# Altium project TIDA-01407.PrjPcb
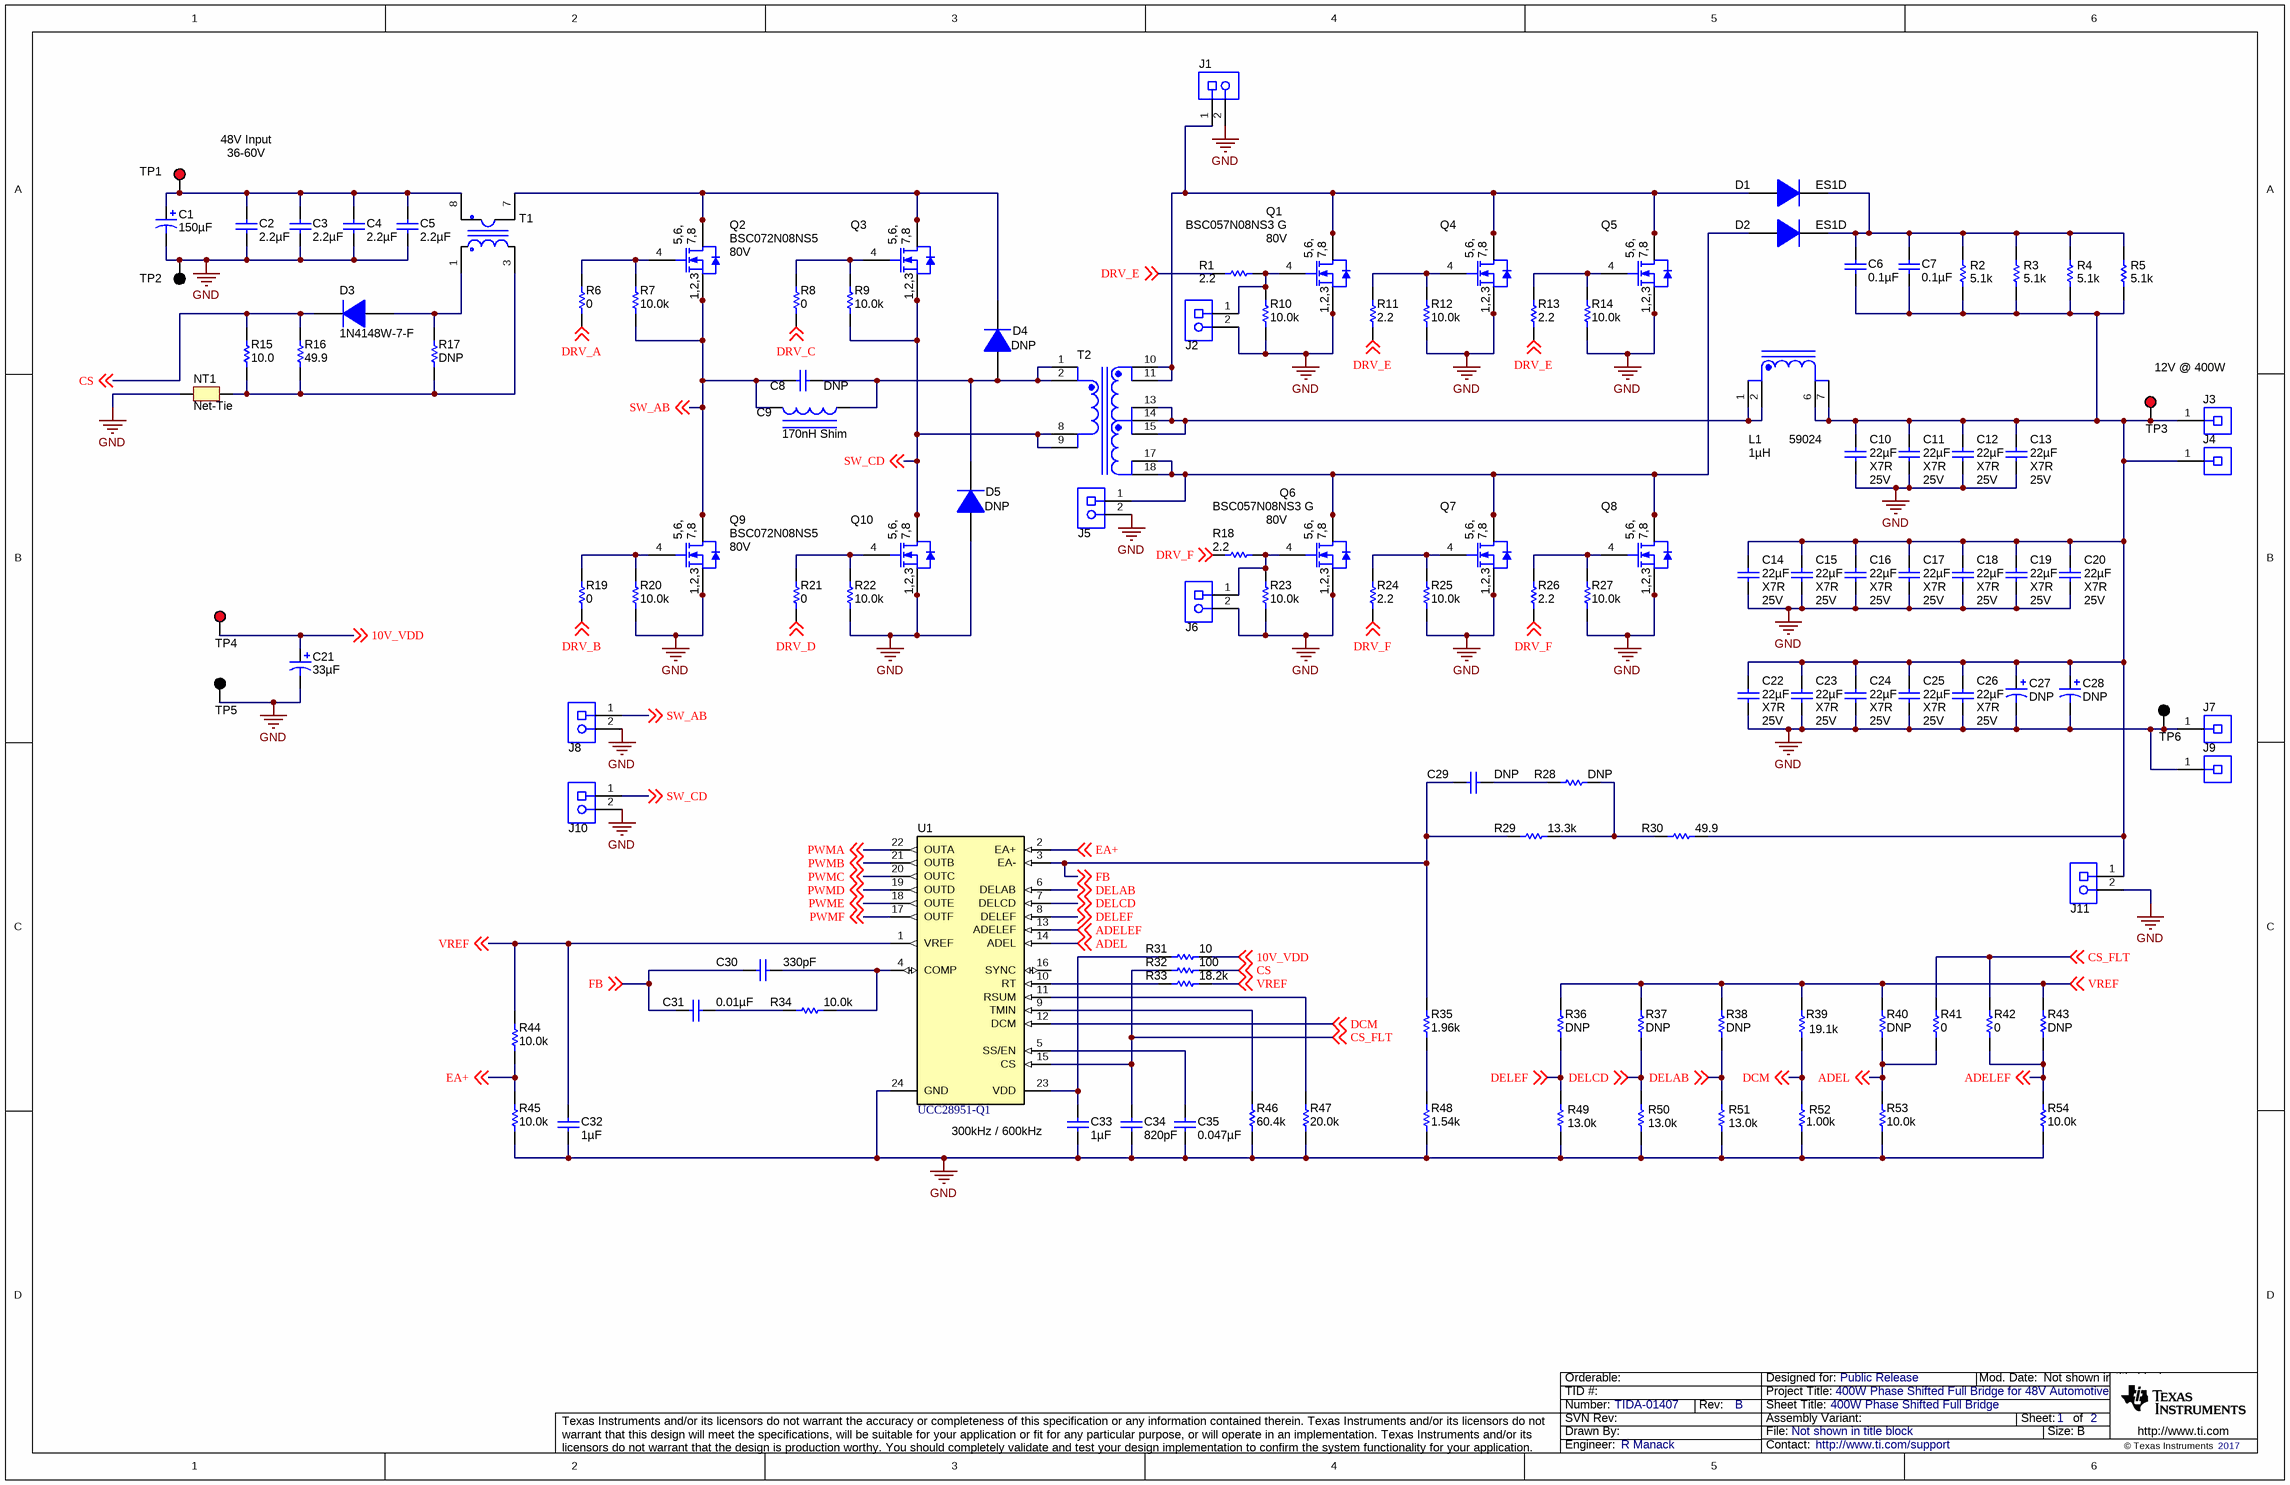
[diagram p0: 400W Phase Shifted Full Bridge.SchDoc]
CopyrightYear: 2017; PCB_Layout: R Manack; PCB_Rev: B; PRJ_Customer: Public Release; PRJ_Engineer: R Manack; PRJ_Number: TIDA-01407; PRJ_Title: 400W Phase Shifted Full Bridge for 48V Automotive; SCH_Rev: B; TechSupport: http://www.ti.com/support
2 sheets, 145 parts. Net scope: global (net labels, ports and power ports of the same name join across sheets).
Board file: TIDA-01407.PcbDoc
Sheets:
  400W Phase Shifted Full Bridge.SchDoc
  Gate Drivers High Side and Low Side.SchDoc

## Sheet 400W Phase Shifted Full Bridge.SchDoc: 400W Phase Shifted Full Bridge
size 431 x 279 mm; Date: Not shown in title block; ApprovedBy: Not shown in title block; CheckedBy: Not shown in title block; Author: Not shown in title block; CompanyName: Not shown in title block; Engineer: Not shown in title block; Organization: Not shown in title block; Address1: Not shown in title block; Address2: Not shown in title block; Address3: Not shown in title block; Address4: Not shown in title block; DocumentNumber: 1; Revision: Use project parameter SCH_Rev; SheetNumber: 1; SheetTotal: 2; PageSetup: Record=PageOptions¦CenterHorizontal=True¦CenterVertical=True¦PrintScale=1.00¦XCorrection=1.00¦YCorrection=1.00¦PrintKind=0¦BorderSize=5000000¦LeftOffset=0¦BottomOffset=0¦Orientation=2¦PaperLength=1000¦PaperWidth=1000¦Scale=100¦PaperSource=15¦PrintQuality=600¦MediaType=1¦DitherType=10¦PaperKind=Letter¦PrintScaleMode=1

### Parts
C1  ValueDisplayed: 150µF  [SM_RADIAL_J16]  (hidden comment: EEV-FK2A151M)
C2  ValueDisplayed: 2.2µF  [1210_270]  (hidden comment: GRM32ER72A225KA35L)
C3  ValueDisplayed: 2.2µF  [1210_270]  (hidden comment: GRM32ER72A225KA35L)
C4  ValueDisplayed: 2.2µF  [1210_270]  (hidden comment: GRM32ER72A225KA35L)
C5  ValueDisplayed: 2.2µF  [1210_270]  (hidden comment: GRM32ER72A225KA35L)
C6  ValueDisplayed: 0.1µF  [1206_180]  (hidden comment: GRM31CR72E104KW03L)
C7  ValueDisplayed: 0.1µF  [1206_180]  (hidden comment: GRM31CR72E104KW03L)
C8  ValueDisplayed: DNP  [1210_270]  (hidden comment: GRM32ER72A225KA35L)
C9  ValueDisplayed: 170nH Shim  [DFE322512C]  (hidden comment: 170nH Custom Shim)
C10  ValueDisplayed: 22µF  Value2: 25V  TempCo: X7R  [1210_270L]  (hidden comment: GRM32ER71E226KE15L)
C11  ValueDisplayed: 22µF  Value2: 25V  TempCo: X7R  [1210_270L]  (hidden comment: GRM32ER71E226KE15L)
C12  ValueDisplayed: 22µF  Value2: 25V  TempCo: X7R  [1210_270L]  (hidden comment: GRM32ER71E226KE15L)
C13  ValueDisplayed: 22µF  Value2: 25V  TempCo: X7R  [1210_270L]  (hidden comment: GRM32ER71E226KE15L)
C14  ValueDisplayed: 22µF  Value2: 25V  TempCo: X7R  [1210_270L]  (hidden comment: GRM32ER71E226KE15L)
C15  ValueDisplayed: 22µF  Value2: 25V  TempCo: X7R  [1210_270L]  (hidden comment: GRM32ER71E226KE15L)
C16  ValueDisplayed: 22µF  Value2: 25V  TempCo: X7R  [1210_270L]  (hidden comment: GRM32ER71E226KE15L)
C17  ValueDisplayed: 22µF  Value2: 25V  TempCo: X7R  [1210_270L]  (hidden comment: GRM32ER71E226KE15L)
C18  ValueDisplayed: 22µF  Value2: 25V  TempCo: X7R  [1210_270L]  (hidden comment: GRM32ER71E226KE15L)
C19  ValueDisplayed: 22µF  Value2: 25V  TempCo: X7R  [1210_270L]  (hidden comment: GRM32ER71E226KE15L)
C20  ValueDisplayed: 22µF  Value2: 25V  TempCo: X7R  [1210_270L]  (hidden comment: GRM32ER71E226KE15L)
C21  ValueDisplayed: 33µF  [Chemi-Con_500x1100]  (hidden comment: EKZE350ELL330ME11D)
C22  ValueDisplayed: 22µF  Value2: 25V  TempCo: X7R  [1210_270L]  (hidden comment: GRM32ER71E226KE15L)
C23  ValueDisplayed: 22µF  Value2: 25V  TempCo: X7R  [1210_270L]  (hidden comment: GRM32ER71E226KE15L)
C24  ValueDisplayed: 22µF  Value2: 25V  TempCo: X7R  [1210_270L]  (hidden comment: GRM32ER71E226KE15L)
C25  ValueDisplayed: 22µF  Value2: 25V  TempCo: X7R  [1210_270L]  (hidden comment: GRM32ER71E226KE15L)
C26  ValueDisplayed: 22µF  Value2: 25V  TempCo: X7R  [1210_270L]  (hidden comment: GRM32ER71E226KE15L)
C27  ValueDisplayed: DNP  [7343-31]  (hidden comment: 16TQC150MYF)
C28  ValueDisplayed: DNP  [7343-31]  (hidden comment: 16TQC150MYF)
C29  ValueDisplayed: DNP  [0603L]  (hidden comment: GRM1885C1H470JA01D)
C30  ValueDisplayed: 330pF  [0603]  (hidden comment: GRM1885C1H331JA01D)
C31  ValueDisplayed: 0.01µF  [0603L]  (hidden comment: GRM188R71H103KA01D)
C32  ValueDisplayed: 1µF  [0603L]  (hidden comment: GRM188R71E105KA12D)
C33  ValueDisplayed: 1µF  [0603L]  (hidden comment: GRM188R71E105KA12D)
C34  ValueDisplayed: 820pF  [0603L]  (hidden comment: GRM1885C1H821JA01D)
C35  ValueDisplayed: 0.047µF  [0603L]  (hidden comment: GRM188R71H473KA61D)
D1  ES1D  [SMA]
D2  ES1D  [SMA]
D3  1N4148W-7-F  [SOD-123]
D4  PartNumber: DNP  [SMA]  (hidden comment: ES1D)
D5  PartNumber: DNP  [SMA]  (hidden comment: ES1D)
J1  PPTC021LFBN-RC  [CONN_PPTC021LFBN-RC]  (value not drawn)
J2  PPTC021LFBN-RC  [CONN_PPTC021LFBN-RC]  (value not drawn)
J3  L35  [TB_L35]  (value not drawn)
J4  L35  [TB_L35]  (value not drawn)
J5  PPTC021LFBN-RC  [CONN_PPTC021LFBN-RC]  (value not drawn)
J6  PPTC021LFBN-RC  [CONN_PPTC021LFBN-RC]  (value not drawn)
J7  L35  [TB_L35]  (value not drawn)
J8  PPTC021LFBN-RC  [CONN_PPTC021LFBN-RC]  (value not drawn)
J9  L35  [TB_L35]  (value not drawn)
J10  PPTC021LFBN-RC  [CONN_PPTC021LFBN-RC]  (value not drawn)
J11  PPTC021LFBN-RC  [CONN_PPTC021LFBN-RC]  (value not drawn)
L1  59024  ValueDisplayed: 1µH  [59024]
NT1  Net-Tie  [Net-Tie_50milWide_30milLong]  (net tie, no BOM)
Q1  BSC057N08NS3 G  value 80V  [PG-TDSON-8]
Q2  BSC072N08NS5  value 80V  [PG-TDSON-8]
Q3  BSC072N08NS5  [PG-TDSON-8]  (value not drawn)
Q4  BSC057N08NS3 G  [PG-TDSON-8]  (value not drawn)
Q5  BSC057N08NS3 G  [PG-TDSON-8]  (value not drawn)
Q6  BSC057N08NS3 G  value 80V  [PG-TDSON-8]
Q7  BSC057N08NS3 G  [PG-TDSON-8]  (value not drawn)
Q8  BSC057N08NS3 G  [PG-TDSON-8]  (value not drawn)
Q9  BSC072N08NS5  value 80V  [PG-TDSON-8]
Q10  BSC072N08NS5  [PG-TDSON-8]  (value not drawn)
R1  ValueDisplayed: 2.2  [0603L]  (hidden comment: CRCW06032R20JNEA)
R2  ValueDisplayed: 5.1k  [2512]  (hidden comment: CRCW25125K10JNEH)
R3  ValueDisplayed: 5.1k  [2512]  (hidden comment: CRCW25125K10JNEH)
R4  ValueDisplayed: 5.1k  [2512]  (hidden comment: CRCW25125K10JNEH)
R5  ValueDisplayed: 5.1k  [2512]  (hidden comment: CRCW25125K10JNEH)
R6  ValueDisplayed: 0  [0603L]  (hidden comment: CRCW06030000Z0EA)
R7  ValueDisplayed: 10.0k  [0603L]  (hidden comment: CRCW060310K0FKEA)
R8  ValueDisplayed: 0  [0603L]  (hidden comment: CRCW06030000Z0EA)
R9  ValueDisplayed: 10.0k  [0603L]  (hidden comment: CRCW060310K0FKEA)
R10  ValueDisplayed: 10.0k  [0603L]  (hidden comment: CRCW060310K0FKEA)
R11  ValueDisplayed: 2.2  [0603L]  (hidden comment: CRCW06032R20JNEA)
R12  ValueDisplayed: 10.0k  [0603L]  (hidden comment: CRCW060310K0FKEA)
R13  ValueDisplayed: 2.2  [0603L]  (hidden comment: CRCW06032R20JNEA)
R14  ValueDisplayed: 10.0k  [0603L]  (hidden comment: CRCW060310K0FKEA)
R15  ValueDisplayed: 10.0  [1206]  (hidden comment: CRCW120610R0FKEA)
R16  ValueDisplayed: 49.9  [1206]  (hidden comment: CRCW120649R9FKEA)
R17  ValueDisplayed: DNP  [0603L]  (hidden comment: CRCW060310K0FKEA)
R18  ValueDisplayed: 2.2  [0603L]  (hidden comment: CRCW06032R20JNEA)
R19  ValueDisplayed: 0  [0603L]  (hidden comment: CRCW06030000Z0EA)
R20  ValueDisplayed: 10.0k  [0603L]  (hidden comment: CRCW060310K0FKEA)
R21  ValueDisplayed: 0  [0603L]  (hidden comment: CRCW06030000Z0EA)
R22  ValueDisplayed: 10.0k  [0603L]  (hidden comment: CRCW060310K0FKEA)
R23  ValueDisplayed: 10.0k  [0603L]  (hidden comment: CRCW060310K0FKEA)
R24  ValueDisplayed: 2.2  [0603L]  (hidden comment: CRCW06032R20JNEA)
R25  ValueDisplayed: 10.0k  [0603L]  (hidden comment: CRCW060310K0FKEA)
R26  ValueDisplayed: 2.2  [0603L]  (hidden comment: CRCW06032R20JNEA)
R27  ValueDisplayed: 10.0k  [0603L]  (hidden comment: CRCW060310K0FKEA)
R28  ValueDisplayed: DNP  [0603L]  (hidden comment: CRCW06030000Z0EA)
R29  ValueDisplayed: 13.3k  [0603L]  (hidden comment: CRCW060313K3FKEA)
R30  ValueDisplayed: 49.9  [0603L]  (hidden comment: CRCW060349R9FKEA)
R31  ValueDisplayed: 10  [0603L]  (hidden comment: CRCW060310R0JNEA)
R32  ValueDisplayed: 100  [0603L]  (hidden comment: CRCW0603100RFKEA)
R33  ValueDisplayed: 18.2k  [0603L]  (hidden comment: CRCW060318K2FKEA)
R34  ValueDisplayed: 10.0k  [0603L]  (hidden comment: CRCW060310K0FKEA)
R35  ValueDisplayed: 1.96k  [0603L]  (hidden comment: CRCW06031K96FKEA)
R36  ValueDisplayed: DNP  [0603L]  (hidden comment: CRCW060310K0FKEA)
R37  ValueDisplayed: DNP  [0603L]  (hidden comment: CRCW060310K0FKEA)
R38  ValueDisplayed: DNP  [0603L]  (hidden comment: CRCW060310K0FKEA)
R39  ValueDisplayed: 19.1k  [0603L]  (hidden comment: CRCW060319K1FKEA)
R40  ValueDisplayed: DNP  [0603L]  (hidden comment: CRCW060310K0FKEA)
R41  ValueDisplayed: 0  [0603L]  (hidden comment: CRCW06030000Z0EA)
R42  ValueDisplayed: 0  [0603L]  (hidden comment: CRCW06030000Z0EA)
R43  ValueDisplayed: DNP  [0603L]  (hidden comment: CRCW060310K0FKEA)
R44  ValueDisplayed: 10.0k  [0603L]  (hidden comment: CRCW060310K0FKEA)
R45  ValueDisplayed: 10.0k  [0603L]  (hidden comment: CRCW060310K0FKEA)
R46  ValueDisplayed: 60.4k  [0603L]  (hidden comment: CRCW060360K4FKEA)
R47  ValueDisplayed: 20.0k  [0603L]  (hidden comment: CRCW060320K0FKEA)
R48  ValueDisplayed: 1.54k  [0603L]  (hidden comment: CRCW06031K54FKEA)
R49  ValueDisplayed: 13.0k  [0603L]  (hidden comment: RC0603FR-0713KL)
R50  ValueDisplayed: 13.0k  [0603L]  (hidden comment: RC0603FR-0713KL)
R51  ValueDisplayed: 13.0k  [0603L]  (hidden comment: RC0603FR-0713KL)
R52  ValueDisplayed: 1.00k  [0603L]  (hidden comment: CRCW06031K00FKEA)
R53  ValueDisplayed: 10.0k  [0603L]  (hidden comment: CRCW060310K0FKEA)
R54  ValueDisplayed: 10.0k  [0603L]  (hidden comment: CRCW060310K0FKEA)
T1  PA1005.100NL  [P82xx]  (value not drawn)
T2  59023  [Payton_59023]  (value not drawn)
TP1  5000  [Keystone5000]  (value not drawn)
TP2  5001  [Keystone5001]  (value not drawn)
TP3  5000  [Keystone5000]  (value not drawn)
TP4  5000  [Keystone5000]  (value not drawn)
TP5  5001  [Keystone5001]  (value not drawn)
TP6  5001  [Keystone5001]  (value not drawn)
U1  UCC28951-Q1  [PW0024A_N]

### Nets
GND: C1.2(-) C2.2 C3.2 C4.2 C5.2 C10.2 C11.2 C12.2 C13.2 C14.2 C15.2 C16.2 C17.2 C18.2 C19.2 C20.2 C21.2(-) C22.2 C23.2 C24.2 C25.2 C26.2 C27.2(-) C28.2(-) C32.2 C33.2 C34.2 C35.2 D5.2(A) J1.2 J2.2 J5.2 J6.2 J7.1 J8.2 J9.1 J10.2 J11.2 NT1.1 Q1.1(S) Q1.2(S) Q1.3(S) Q4.1(S) Q4.2(S) Q4.3(S) Q5.1(S) Q5.2(S) Q5.3(S) Q6.1(S) Q6.2(S) Q6.3(S) Q7.1(S) Q7.2(S) Q7.3(S) Q8.1(S) Q8.2(S) Q8.3(S) Q9.1(S) Q9.2(S) Q9.3(S) Q10.1(S) Q10.2(S) Q10.3(S) R10.1 R12.1 R14.1 R20.1 R22.1 R23.1 R25.1 R27.1 R45.1 R46.1 R47.1 R48.1 R49.1 R50.1 R51.1 R52.1 R53.1 R54.1 TP2.1 TP5.1 TP6.1 U1.24(GND)
10V_VDD: C21.1(+) R31.2 TP4.1 ; off-sheet 10V_VDD
ADEL: R40.1 R41.1 R53.2 U1.14(ADEL) ; off-sheet ADEL
ADELEF: R42.1 R43.1 R54.2 U1.13(ADELEF) ; off-sheet ADELEF
CS: D3.1(K) R15.2 R16.2 R32.2 ; off-sheet CS
CS_FLT: C34.1 R32.1 R41.2 R42.2 U1.15(CS) ; off-sheet CS_FLT
DCM: R39.1 R52.2 U1.12(DCM) ; off-sheet DCM
DELAB: R38.1 R51.2 U1.6(DELAB) ; off-sheet DELAB
DELCD: R37.1 R50.2 U1.7(DELCD) ; off-sheet DELCD
DELEF: R36.1 R49.2 U1.8(DELEF) ; off-sheet DELEF
DRV_A: R6.1 ; off-sheet DRV_A
DRV_B: R19.1 ; off-sheet DRV_B
DRV_C: R8.1 ; off-sheet DRV_C
DRV_D: R21.1 ; off-sheet DRV_D
DRV_E: R1.2 R11.1 R13.1 ; off-sheet DRV_E
DRV_F: R18.2 R24.1 R26.1 ; off-sheet DRV_F
EA+: R44.1 R45.2 U1.2(EA+) ; off-sheet EA+
FB: C29.1 C30.2 C31.2 R29.1 R35.2 U1.3(EA-) ; off-sheet FB
PWMA: U1.22(OUTA) ; off-sheet PWMA
PWMB: U1.21(OUTB) ; off-sheet PWMB
PWMC: U1.20(OUTC) ; off-sheet PWMC
PWMD: U1.19(OUTD) ; off-sheet PWMD
PWME: U1.18(OUTE) ; off-sheet PWME
PWMF: U1.17(OUTF) ; off-sheet PWMF
SW_AB: C8.1 C9.2 J8.1 Q2.1(S) Q2.2(S) Q2.3(S) Q9.5(D) Q9.6(D) Q9.7(D) Q9.8(D) Q9.9(D) R7.1 ; off-sheet SW_AB
SW_CD: J10.1 Q3.1(S) Q3.2(S) Q3.3(S) Q10.5(D) Q10.6(D) Q10.7(D) Q10.8(D) Q10.9(D) R9.1 T2.8 T2.9 ; off-sheet SW_CD
VREF: C32.1 R33.2 R36.2 R37.2 R38.2 R39.2 R40.2 R43.2 R44.2 U1.1(VREF) ; off-sheet VREF
NetC1_1: C1.1(+) C2.1 C3.1 C4.1 C5.1 T1.8 TP1.1
NetC6_1: C6.1 C7.1 D1.1(K) D2.1(K) R2.2 R3.2 R4.2 R5.2
NetC6_2: C6.2 C7.2 C10.1 C11.1 C12.1 C13.1 C14.1 C15.1 C16.1 C17.1 C18.1 C19.1 C20.1 C22.1 C23.1 C24.1 C25.1 C26.1 C27.1(+) C28.1(+) J3.1 J4.1 J11.1 L1.6 L1.7 R2.1 R3.1 R4.1 R5.1 R30.2 TP3.1
NetC8_2: C8.2 C9.1 D4.2(A) D5.1(K) T2.1 T2.2
NetC29_2: C29.2 R28.2
NetC30_1: C30.1 R34.2 U1.4(COMP)
NetC31_1: C31.1 R34.1
NetC33_1: C33.1 R31.1 U1.23(VDD)
NetC35_1: C35.1 U1.5(SS/EN)
NetD1_2: D1.2(A) J1.1 Q1.5(D) Q1.6(D) Q1.7(D) Q1.8(D) Q1.9(D) Q4.5(D) Q4.6(D) Q4.7(D) Q4.8(D) Q4.9(D) Q5.5(D) Q5.6(D) Q5.7(D) Q5.8(D) Q5.9(D) T2.10 T2.11
NetD2_2: D2.2(A) J5.1 Q6.5(D) Q6.6(D) Q6.7(D) Q6.8(D) Q6.9(D) Q7.5(D) Q7.6(D) Q7.7(D) Q7.8(D) Q7.9(D) Q8.5(D) Q8.6(D) Q8.7(D) Q8.8(D) Q8.9(D) T2.17 T2.18
NetD3_2: D3.2(A) R17.2 T1.1
NetD4_1: D4.1(K) Q2.5(D) Q2.6(D) Q2.7(D) Q2.8(D) Q2.9(D) Q3.5(D) Q3.6(D) Q3.7(D) Q3.8(D) Q3.9(D) T1.7
NetJ2_1: J2.1 Q1.4(G) R1.1 R10.2
NetJ6_1: J6.1 Q6.4(G) R18.1 R23.2
NetL1_1: L1.1 L1.2 T2.13 T2.14 T2.15
NetNT1_2: NT1.2 R15.1 R16.1 R17.1 T1.3
NetQ2_4: Q2.4(G) R6.2 R7.2
NetQ3_4: Q3.4(G) R8.2 R9.2
NetQ4_4: Q4.4(G) R11.2 R12.2
NetQ5_4: Q5.4(G) R13.2 R14.2
NetQ7_4: Q7.4(G) R24.2 R25.2
NetQ8_4: Q8.4(G) R26.2 R27.2
NetQ9_4: Q9.4(G) R19.2 R20.2
NetQ10_4: Q10.4(G) R21.2 R22.2
NetR28_1: R28.1 R29.2 R30.1
NetR33_1: R33.1 U1.10(RT)
NetR35_1: R35.1 R48.2
NetR46_2: R46.2 U1.9(TMIN)
NetR47_2: R47.2 U1.11(RSUM)

Not connected (* = marked no-connect by the designer): U1 16(SYNC)

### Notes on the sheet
- 48V Input
- 36-60V
- 12V @ 400W
- 300kHz / 600kHz

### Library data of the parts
C1 = EEV-FK2A151M: CAP, AL, 150 µF, 100 V, +/- 20%, 0.17 ohm, AEC-Q200 Grade 2, SMD; Manufacturer: Panasonic; Polarized: Y; CompType: Capacitor; Value: 150uF; U/M: EA; Cap_F: 0.00015; Tolerance_%: 20; VDC_V: 100; Value2: 100V; ESR_ohm: 0.17; IRMS_A: 0.793; TaMin_C: -55; TaMax_C: 105; Cap_Case: J16; SizeAreaWB_mm2: 399; SizeArea_mm2: 323; SizeX_mm: 19; SizeY_mm: 17; SizeZ_mm: 16.5; AEC Category: Q200; AEC Grade: 2
C2-C5 = GRM32ER72A225KA35L: CAP, CERM, 2.2 µF, 100 V, +/- 10%, X7R, 1210; Manufacturer: MuRata; Polarized: N; CompType: Capacitor; Value: 2.2uF; U/M: EA; Cap_F: 0.0000022; Tolerance_%: 10; ESR_ohm: 0.007; Value1: 0.007 ohm; VDC_V: 100; Value2: 100V; IRMS_A: 4.4; TaMin_C: -55; TaMax_C: 125; Cap_Case: 1210; SizeArea_mm2: 8; SizeAreaWB_mm2: 14.7; SizeX_mm: 3.2; SizeY_mm: 2.5; SizeZ_mm: 2.7; AEC Category: Q200
C6 C7 = GRM31CR72E104KW03L: CAP, CERM, 0.1 µF, 250 V, +/- 10%, X7R, 1206; Manufacturer: MuRata; Polarized: N; CompType: Capacitor; Value: 0.1uF; U/M: EA; Cap_F: 0.0000001; Tolerance_%: 10; Value1: Unknown; VDC_V: 250; Value2: 250V; TaMin_C: -55; TaMax_C: 125; Cap_Case: 1206; SizeArea_mm2: 5.12; SizeAreaWB_mm2: 10.92; SizeX_mm: 3.2; SizeY_mm: 1.6; SizeZ_mm: 1.8; AEC Category: Q200
C8 = GRM32ER72A225KA35L: CAP, CERM, 2.2 µF, 100 V, +/- 10%, X7R, 1210; Manufacturer: MuRata; Polarized: N; CompType: Capacitor; Value: DNP; U/M: EA; Cap_F: 0.0000022; Tolerance_%: 10; ESR_ohm: 0.007; Value1: 0.007 ohm; VDC_V: 100; Value2: 100V; IRMS_A: 4.4; TaMin_C: -55; TaMax_C: 125; Cap_Case: 1210; SizeArea_mm2: 8; SizeAreaWB_mm2: 14.7; SizeX_mm: 3.2; SizeY_mm: 2.5; SizeZ_mm: 2.7; AEC Category: Q200
C9 = 1277AS-H-R68M=P2: Inductor, Flat Wire, 680 nH, 3.5 A, 0.035 ohm, SMD; Value2: 3.5A; SizeArea_mm2: 9.18; SizeAreaWB_mm2: 16.28; SizeX_mm: 3.4; SizeY_mm: 2.7; SizeZ_mm: 1.2; AEC Category: Q200; AEC Qualified: N; Ind_H: 680.0E-9; Imax_A: 3.5; Irms: 3.5A @ 40C rise; Isat: 4.2A @ 30% inductance drop; DCR_ohm: 0.035
C10-C20 C22-C26 = GRM32ER71E226KE15L: CAP, CERM, 22 µF, 25 V, +/- 10%, X7R, 1210; Manufacturer: MuRata; Polarized: N; CompType: Capacitor; Value: 22uF; U/M: EA; Cap_F: 0.000022; Tolerance_%: 10; Value1: Unknown; VDC_V: 25; TaMin_C: -55; TaMax_C: 125; Cap_Case: 1210; SizeArea_mm2: 8; SizeAreaWB_mm2: 14.7; SizeX_mm: 3.2; SizeY_mm: 2.5; SizeZ_mm: 2.7; AEC Category: Q200
C21 = EKZE350ELL330ME11D: CAP, AL, 33 µF, 35 V, +/- 20%, TH; Manufacturer: Chemi-Con; Polarized: Y; CompType: Capacitor; Value: 33uF; U/M: EA; Cap_F: 0.000033; Tolerance_%: 20; Value1: Unknown; VDC_V: 35; Value2: 35V; IRMS_A: 0.25; TaMin_C: -40; TaMax_C: 105; Cap_Case: 5x11; SizeAreaWB_mm2: 49; SizeArea_mm2: 25; SizeX_mm: 5; SizeZ_mm: 12.5; AEC Category: Q200; AEC Qualified: N
C27 C28 = 16TQC150MYF: CAP, Tantalum Polymer, 150 µF, 16 V, +/- 20%, 0.05 ohm, 7343-31 SMD; Manufacturer: Panasonic; Polarized: Y; CompType: Capacitor; Value: DNP; U/M: EA; Cap_F: 0.00015; Tolerance_%: 20; VDC_V: 16; Value2: 16V; ESR_ohm: 0.05; IRMS_A: 1.8; TaMin_C: -55; TaMax_C: 105; Cap_Case: 7.3x2.8x4.3; SizeAreaWB_mm2: 58.59; SizeArea_mm2: 31.39; SizeX_mm: 7.3; SizeY_mm: 4.3; SizeZ_mm: 3.1; AEC Category: Q200; AEC Qualified: N
C29 = GRM1885C1H470JA01D: CAP, CERM, 47 pF, 50 V, +/- 5%, C0G/NP0, 0603; Manufacturer: MuRata; Polarized: N; CompType: Capacitor; Value: DNP; U/M: EA; Cap_F: 0.000000000047; Tolerance_%: 5; Value1: Unknown; VDC_V: 50; Value2: 50V; TaMin_C: -55; TaMax_C: 125; Cap_Case: 0603; SizeArea_mm2: 1.28; SizeAreaWB_mm2: 4.68; SizeX_mm: 1.6; SizeY_mm: 0.8; SizeZ_mm: 1; AEC Category: Q200
C30 = GRM1885C1H331JA01D: CAP, CERM, 330 pF, 50 V, +/- 5%, C0G/NP0, 0603; Manufacturer: MuRata; Polarized: N; CompType: Capacitor; Value: 330pF; U/M: EA; Cap_F: 0.00000000033; Tolerance_%: 5; Value1: Unknown; VDC_V: 50; Value2: 50V; TaMin_C: -55; TaMax_C: 125; SizeArea_mm2: 1.28; SizeAreaWB_mm2: 4.68; SizeX_mm: 1.6; SizeY_mm: 0.8; SizeZ_mm: 1; AEC Category: Q200
C31 = GRM188R71H103KA01D: CAP, CERM, 0.01 µF, 50 V, +/- 10%, X7R, 0603; Manufacturer: MuRata; Polarized: N; CompType: Capacitor; Value: 0.01uF; U/M: EA; Cap_F: 0.00000001; Tolerance_%: 10; Value1: Unknown; VDC_V: 50; Value2: 50V; TaMin_C: -55; TaMax_C: 125; Cap_Case: 0603; SizeArea_mm2: 1.28; SizeAreaWB_mm2: 4.68; SizeX_mm: 1.6; SizeY_mm: 0.8; SizeZ_mm: 1; AEC Category: Q200
C32 C33 = GRM188R71E105KA12D: CAP, CERM, 1 µF, 25 V, +/- 10%, X7R, 0603; Manufacturer: MuRata; Polarized: N; CompType: Capacitor; Value: 1uF; U/M: EA; Cap_F: 0.000001; Tolerance_%: 10; Value1: Unknown; VDC_V: 25; Value2: 25V; TaMin_C: -55; TaMax_C: 125; Cap_Case: 0603; SizeArea_mm2: 1.28; SizeAreaWB_mm2: 4.68; SizeX_mm: 1.6; SizeY_mm: 0.8; SizeZ_mm: 1; AEC Category: Q200
C34 = GRM1885C1H821JA01D: CAP, CERM, 820 pF, 50 V, +/- 5%, C0G/NP0, 0603; Manufacturer: MuRata; Polarized: N; CompType: Capacitor; Value: 820pF; U/M: EA; Cap_F: 0.00000000082; Tolerance_%: 5; Value1: Unknown; VDC_V: 50; Value2: 50V; TaMin_C: -55; TaMax_C: 125; Cap_Case: 0603; SizeArea_mm2: 1.28; SizeAreaWB_mm2: 4.68; SizeX_mm: 1.6; SizeY_mm: 0.8; SizeZ_mm: 1; AEC Category: Q200
C35 = GRM188R71H473KA61D: CAP, CERM, 0.047 µF, 50 V, +/- 10%, X7R, 0603; Manufacturer: MuRata; Polarized: N; CompType: Capacitor; Value: 0.047uF; U/M: EA; Cap_F: 0.000000047; Tolerance_%: 10; Value1: Unknown; VDC_V: 50; Value2: 50V; TaMin_C: -55; TaMax_C: 125; Cap_Case: 0603; SizeArea_mm2: 1.28; SizeAreaWB_mm2: 4.68; SizeX_mm: 1.6; SizeY_mm: 0.8; SizeZ_mm: 1; AEC Category: Q200
D1 D2 D4 D5 = ES1D-13-F: Diode, Ultrafast, 200 V, 1 A, SMA; Manufacturer: Diodes Inc.; U/M: EA; Vf_V: 0.92; Value: 200V; Value1: 1A; Value2: 0.92V; Io_A: 1; Vr_V: 200; TJmax_C: 150; RJC_CperW: 25; SizeAreaWB_mm2: 37.3428; SizeArea_mm2: 16.3228; SizeX_mm: 5.59; SizeY_mm: 2.92; SizeZ_mm: 2.87; AEC Category: Q101
D3 = 1N4148W-7-F: Diode, Ultrafast, 100 V, 0.15 A, SOD-123; Manufacturer: Diodes Inc.; U/M: EA; Vf_V: 1.25; Value: 100V; Value1: 0.15A; Value2: 1.25V; Io_A: 0.15; Vr_V: 100; TJmax_C: 150; SizeAreaWB_mm2: 13.095; SizeArea_mm2: 6.545; SizeX_mm: 3.85; SizeY_mm: 1.7; SizeZ_mm: 1.35; AEC Category: Q101
J1 J2 J5 J6 J8 J10 J11 = PPTC021LFBN-RC: Receptacle, 100mil, 2x1, Tin, TH; Manufacturer: Sullins Connector Solutions; SymbolCreator: a0412235
J3 J4 J7 J9 = L35: Connector, L Type Copper Single Conductor, TH; Manufacturer: Thomas & Betts; SymbolCreator: a0799628; Gender: Female; Row_Count: 1
L1 = 59024: Inductor, 1 µH, 47 A, TH; Manufacturer: Payton; SymbolCreator: Altium; Ind_H: 1.0E-6; Value: 1uH; Imax_A: 47; Irms: 47A @ C rise; Value2: 47A; AEC Category: Q200; AEC Qualified: N
NT1 = Net-Tie: Single point connection between nets.; SymbolCreator: codlsc
Q1 Q6 = BSC057N08NS3 G: MOSFET, N-CH, 80 V, 100 A, PG-TDSON-8; Manufacturer: Infineon Technologies; Alternate Manufacturer: None; U/M: EA; ChType: N; VdsMax_V: 80; Value1: ? ohm; Value2: 42 nC; QgTyp_nC: 42; Vgs_V: 20; IdsMax_A: 100; SizeAreaWB_mm2: 55.131; SizeArea_mm2: 29.351; SizeX_mm: 5.99; SizeY_mm: 4.9; SizeZ_mm: 1.12; AEC Category: Q101
Q2 Q9 = BSC072N08NS5ATMA1: MOSFET, N-CH, 80 V, 74 A, PG-TDSON-8; Manufacturer: Infineon Technologies; Alternate Manufacturer: None; U/M: EA; ChType: N; VdsMax_V: 80; Value1: ? ohm; Value2: 24 nC; QgTyp_nC: 24; Vgs_V: 20; IdsMax_A: 74; SizeAreaWB_mm2: 55.131; SizeArea_mm2: 29.351; SizeX_mm: 5.99; SizeY_mm: 4.9; SizeZ_mm: 1.12; AEC Category: Q101
Q3 Q10 = BSC072N08NS5ATMA1: MOSFET, N-CH, 80 V, 74 A, PG-TDSON-8; Manufacturer: Infineon Technologies; Alternate Manufacturer: None; U/M: EA; ChType: N; Value: 80V; VdsMax_V: 80; Value1: ? ohm; Value2: 24 nC; QgTyp_nC: 24; Vgs_V: 20; IdsMax_A: 74; SizeAreaWB_mm2: 55.131; SizeArea_mm2: 29.351; SizeX_mm: 5.99; SizeY_mm: 4.9; SizeZ_mm: 1.12; AEC Category: Q101
Q4 Q5 Q7 Q8 = BSC057N08NS3 G: MOSFET, N-CH, 80 V, 100 A, PG-TDSON-8; Manufacturer: Infineon Technologies; Alternate Manufacturer: None; U/M: EA; ChType: N; Value: 80V; VdsMax_V: 80; Value1: ? ohm; Value2: 42 nC; QgTyp_nC: 42; Vgs_V: 20; IdsMax_A: 100; SizeAreaWB_mm2: 55.131; SizeArea_mm2: 29.351; SizeX_mm: 5.99; SizeY_mm: 4.9; SizeZ_mm: 1.12; AEC Category: Q101
R1 R11 R13 R18 R24 R26 = CRCW06032R20JNEA: RES, 2.2, 5%, 0.1 W, 0603; Manufacturer: Vishay-Dale; CompType: Resistor; Value: 2.2; Value_Code: 2R20; Tolerance_%: 5; Power_W: 0.1; Value2: 0.1W; VDC_V: 75; TempCo: 200 ppm/C; SizeArea_mm2: 1.28; SizeX_mm: 1.6; SizeY_mm: 0.8; SizeZ_mm: 1; EIA_Code: E24; U/M: EA; AEC Category: Q200
R2-R5 = CRCW25125K10JNEH: RES, 5.1 k, 5%, 1 W, AEC-Q200 Grade 0, 2512; Manufacturer: Vishay-Dale; CompType: Resistor; Value: 5.1k; Res_ohm: 5100; Value_Code: 5k10; Tolerance_%: 5; Power_W: 1; Value2: 1W; VDC_V: 500; TempCo: 200 ppm/C; SizeArea_mm2: 20.16; SizeX_mm: 6.3; SizeY_mm: 3.2; SizeZ_mm: 0.71; EIA_Code: E24; U/M: EA; AEC Category: Q200; AEC Qualified: Y; AEC Grade: 0
R6 R8 R19 R21 R41 R42 = CRCW06030000Z0EA: RES, 0, 5%, 0.1 W, 0603; Manufacturer: Vishay-Dale; CompType: Resistor; Value: 0; Value_Code: 0000; Tolerance_%: 5; Power_W: 0.1; Value2: 0.1W; VDC_V: 75; TempCo: 200 ppm/C; SizeArea_mm2: 1.28; SizeX_mm: 1.6; SizeY_mm: 0.8; SizeZ_mm: 1; EIA_Code: E24; U/M: EA; AEC Category: Q200
R7 R9 R10 R12 R14 R20 R22 R23 R25 R27 R34 R44 R45 R53 R54 = CRCW060310K0FKEA: RES, 10.0 k, 1%, 0.1 W, 0603; Manufacturer: Vishay-Dale; CompType: Resistor; Value: 10.0k; Res_ohm: 10000; Value_Code: 10k0; Tolerance_%: 1; Power_W: 0.1; Value2: 0.1W; VDC_V: 75; TempCo: 100 ppm/C; SizeArea_mm2: 1.28; SizeX_mm: 1.6; SizeY_mm: 0.8; EIA_Code: E96; U/M: EA; AEC Category: Q200
R15 = CRCW120610R0FKEA: RES, 10.0, 1%, 0.25 W, 1206; Manufacturer: Vishay-Dale; CompType: Resistor; Value: 10.0; Res_ohm: 10; Value_Code: 10R0; Tolerance_%: 1; Power_W: 0.25; Value2: 0.25W; VDC_V: 200; TempCo: 100 ppm/C; SizeArea_mm2: 5.12; SizeX_mm: 3.2; SizeY_mm: 1.6; SizeZ_mm: 1.35; EIA_Code: E96; U/M: EA; AEC Category: Q200
R16 = CRCW120649R9FKEA: RES, 49.9, 1%, 0.25 W, 1206; Manufacturer: Vishay-Dale; CompType: Resistor; Value: 49.9; Value_Code: 49R9; Tolerance_%: 1; Power_W: 0.25; Value2: 0.25W; VDC_V: 200; TempCo: 100 ppm/C; SizeArea_mm2: 5.12; SizeX_mm: 3.2; SizeY_mm: 1.6; SizeZ_mm: 1.35; EIA_Code: E96; U/M: EA; AEC Category: Q200
R17 R36-R38 R40 R43 = CRCW060310K0FKEA: RES, 10.0 k, 1%, 0.1 W, 0603; Manufacturer: Vishay-Dale; CompType: Resistor; Value: DNP; Res_ohm: 10000; Value_Code: 10k0; Tolerance_%: 1; Power_W: 0.1; Value2: 0.1W; VDC_V: 75; TempCo: 100 ppm/C; SizeArea_mm2: 1.28; SizeX_mm: 1.6; SizeY_mm: 0.8; EIA_Code: E96; U/M: EA; AEC Category: Q200
R28 = CRCW06030000Z0EA: RES, 0, 5%, 0.1 W, 0603; Manufacturer: Vishay-Dale; CompType: Resistor; Value: DNP; Res_ohm: 0; Value_Code: 0000; Tolerance_%: 5; Power_W: 0.1; Value2: 0.1W; VDC_V: 75; TempCo: 200 ppm/C; SizeArea_mm2: 1.28; SizeX_mm: 1.6; SizeY_mm: 0.8; SizeZ_mm: 1; EIA_Code: E24; U/M: EA; AEC Category: Q200
R29 = CRCW060313K3FKEA: RES, 13.3 k, 1%, 0.1 W, 0603; Manufacturer: Vishay-Dale; CompType: Resistor; Value: 13.3k; Res_ohm: 13300; Value_Code: 13k3; Tolerance_%: 1; Power_W: 0.1; Value2: 0.1W; VDC_V: 75; TempCo: 100 ppm/C; SizeArea_mm2: 1.28; SizeX_mm: 1.6; SizeY_mm: 0.8; EIA_Code: E96; U/M: EA; AEC Category: Q200
R30 = CRCW060349R9FKEA: RES, 49.9, 1%, 0.1 W, 0603; Manufacturer: Vishay-Dale; CompType: Resistor; Value: 49.9; Value_Code: 49R9; Tolerance_%: 1; Power_W: 0.1; Value2: 0.1W; VDC_V: 75; TempCo: 100 ppm/C; SizeArea_mm2: 1.28; SizeX_mm: 1.6; SizeY_mm: 0.8; EIA_Code: E96; U/M: EA; AEC Category: Q200
R31 = CRCW060310R0JNEA: RES, 10, 5%, 0.1 W, 0603; Manufacturer: Vishay-Dale; CompType: Resistor; Value: 10; Value_Code: 10R0; Tolerance_%: 5; Power_W: 0.1; Value2: 0.1W; VDC_V: 75; TempCo: 200 ppm/C; SizeArea_mm2: 1.28; SizeX_mm: 1.6; SizeY_mm: 0.8; SizeZ_mm: 1; EIA_Code: E24; U/M: EA; AEC Category: Q200
R32 = CRCW0603100RFKEA: RES, 100, 1%, 0.1 W, 0603; Manufacturer: Vishay-Dale; CompType: Resistor; Value: 100; Value_Code: 100R; Tolerance_%: 1; Power_W: 0.1; Value2: 0.1W; VDC_V: 75; TempCo: 100 ppm/C; SizeArea_mm2: 1.28; SizeX_mm: 1.6; SizeY_mm: 0.8; EIA_Code: E96; U/M: EA; AEC Category: Q200
R33 = CRCW060318K2FKEA: RES, 18.2 k, 1%, 0.1 W, 0603; Manufacturer: Vishay-Dale; CompType: Resistor; Value: 18.2k; Res_ohm: 18200; Value_Code: 18k2; Tolerance_%: 1; Power_W: 0.1; Value2: 0.1W; VDC_V: 75; TempCo: 100 ppm/C; SizeArea_mm2: 1.28; SizeX_mm: 1.6; SizeY_mm: 0.8; EIA_Code: E96; U/M: EA; AEC Category: Q200
R35 = CRCW06031K96FKEA: RES, 1.96 k, 1%, 0.1 W, 0603; Manufacturer: Vishay-Dale; CompType: Resistor; Value: 1.96k; Res_ohm: 1960; Value_Code: 1k96; Tolerance_%: 1; Power_W: 0.1; Value2: 0.1W; VDC_V: 75; TempCo: 100 ppm/C; SizeArea_mm2: 1.28; SizeX_mm: 1.6; SizeY_mm: 0.8; EIA_Code: E96; U/M: EA; AEC Category: Q200
R39 = CRCW060319K1FKEA: RES, 19.1 k, 1%, 0.1 W, 0603; Manufacturer: Vishay-Dale; CompType: Resistor; Value: 19.1k; Res_ohm: 19100; Value_Code: 19k1; Tolerance_%: 1; Power_W: 0.1; Value2: 0.1W; VDC_V: 75; TempCo: 100 ppm/C; SizeArea_mm2: 1.28; SizeX_mm: 1.6; SizeY_mm: 0.8; EIA_Code: E96; U/M: EA; AEC Category: Q200
R46 = CRCW060360K4FKEA: RES, 60.4 k, 1%, 0.1 W, 0603; Manufacturer: Vishay-Dale; CompType: Resistor; Value: 60.4k; Res_ohm: 60400; Value_Code: 60k4; Tolerance_%: 1; Power_W: 0.1; Value2: 0.1W; VDC_V: 75; TempCo: 100 ppm/C; SizeArea_mm2: 1.28; SizeX_mm: 1.6; SizeY_mm: 0.8; EIA_Code: E96; U/M: EA; AEC Category: Q200
R47 = CRCW060320K0FKEA: RES, 20.0 k, 1%, 0.1 W, 0603; Manufacturer: Vishay-Dale; CompType: Resistor; Value: 20.0k; Res_ohm: 20000; Value_Code: 20k0; Tolerance_%: 1; Power_W: 0.1; Value2: 0.1W; VDC_V: 75; TempCo: 100 ppm/C; SizeArea_mm2: 1.28; SizeX_mm: 1.6; SizeY_mm: 0.8; EIA_Code: E96; U/M: EA; AEC Category: Q200
R48 = CRCW06031K54FKEA: RES, 1.54 k, 1%, 0.1 W, 0603; Manufacturer: Vishay-Dale; CompType: Resistor; Value: 1.54k; Res_ohm: 1540; Value_Code: 1k54; Tolerance_%: 1; Power_W: 0.1; Value2: 0.1W; VDC_V: 75; TempCo: 100 ppm/C; SizeArea_mm2: 1.28; SizeX_mm: 1.6; SizeY_mm: 0.8; EIA_Code: E96; U/M: EA; AEC Category: Q200
R49-R51 = RC0603FR-0713KL: RES, 13.0 k, 1%, 0.1 W, 0603; Manufacturer: Yageo America; CompType: Resistor; Value: 13.0k; Res_ohm: 13000; Value_Code: 13k0; Tolerance_%: 1; Power_W: 0.1; Value2: 0.1W; VDC_V: 150; TempCo: 200 ppm/C; SizeArea_mm2: 1.28; SizeX_mm: 1.6; SizeY_mm: 0.8; EIA_Code: E96; U/M: EA; AEC Category: Q200
R52 = CRCW06031K00FKEA: RES, 1.00 k, 1%, 0.1 W, 0603; Manufacturer: Vishay-Dale; CompType: Resistor; Value: 1.00k; Res_ohm: 1000; Value_Code: 1k00; Tolerance_%: 1; Power_W: 0.1; Value2: 0.1W; VDC_V: 75; TempCo: 100 ppm/C; SizeArea_mm2: 1.28; SizeX_mm: 1.6; SizeY_mm: 0.8; EIA_Code: E96; U/M: EA; AEC Category: Q200
T1 = PA1005.100NL: SMT Current Sense Tranformer; Manufacturer: Pulse Engineering; SymbolCreator: a0412235; Rs1: 5.5; CompType: Transformer
T2 = 59023: Transformer, TH; Manufacturer: Payton; SymbolCreator: Altium; Ns1toNp: 0.4
TP1 TP3 TP4 = 5000: Test Point, Miniature, Red, TH; Manufacturer: Keystone; CompType: Test Point Loop; ContactFinish: Silver
TP2 TP5 TP6 = 5001: Test Point, Miniature, Black, TH; Manufacturer: Keystone; CompType: Test Point Loop; ContactFinish: Silver
U1 = UCC28950PWR: Green Phase-Shifted Full-Bridge Controller with Synchronous Rectification with Current Mode Control, 97 % Duty Cycle, -40 to +125 degC, 24-pin TSSOP (PW), Green (RoHS & no Sb/Br); PartNumber: UCC28951QPWRQ1; Manufacturer: Texas Instruments; Alternate PartNumber: Equivalent; Duty Cycle(Max)(%): 97; Frequency(Max)(kHz): 1000; Rating: Catalog; Regulated Outputs(#): 1; SubFamily: PWM Controller; UVLO Thresholds On/Off(V): 6.75min/6.15min

## Sheet Gate Drivers High Side and Low Side.SchDoc: Gate Driver Primiary and Secondary
size 431 x 279 mm; Date: Not shown in title block; ApprovedBy: Not shown in title block; CheckedBy: Not shown in title block; Author: Not shown in title block; CompanyName: Not shown in title block; Engineer: Not shown in title block; Organization: Not shown in title block; Address1: Not shown in title block; Address2: Not shown in title block; Address3: Not shown in title block; Address4: Not shown in title block; DocumentNumber: 2; Revision: Use project parameter SCH_Rev; SheetNumber: 2; SheetTotal: 2; PageSetup: Record=PageOptions¦CenterHorizontal=True¦CenterVertical=True¦PrintScale=1.00¦XCorrection=1.00¦YCorrection=1.00¦PrintKind=0¦BorderSize=5000000¦LeftOffset=0¦BottomOffset=0¦Orientation=2¦PaperLength=1000¦PaperWidth=1000¦Scale=100¦PaperSource=15¦PrintQuality=600¦MediaType=1¦DitherType=10¦PaperKind=Letter¦PrintScaleMode=1
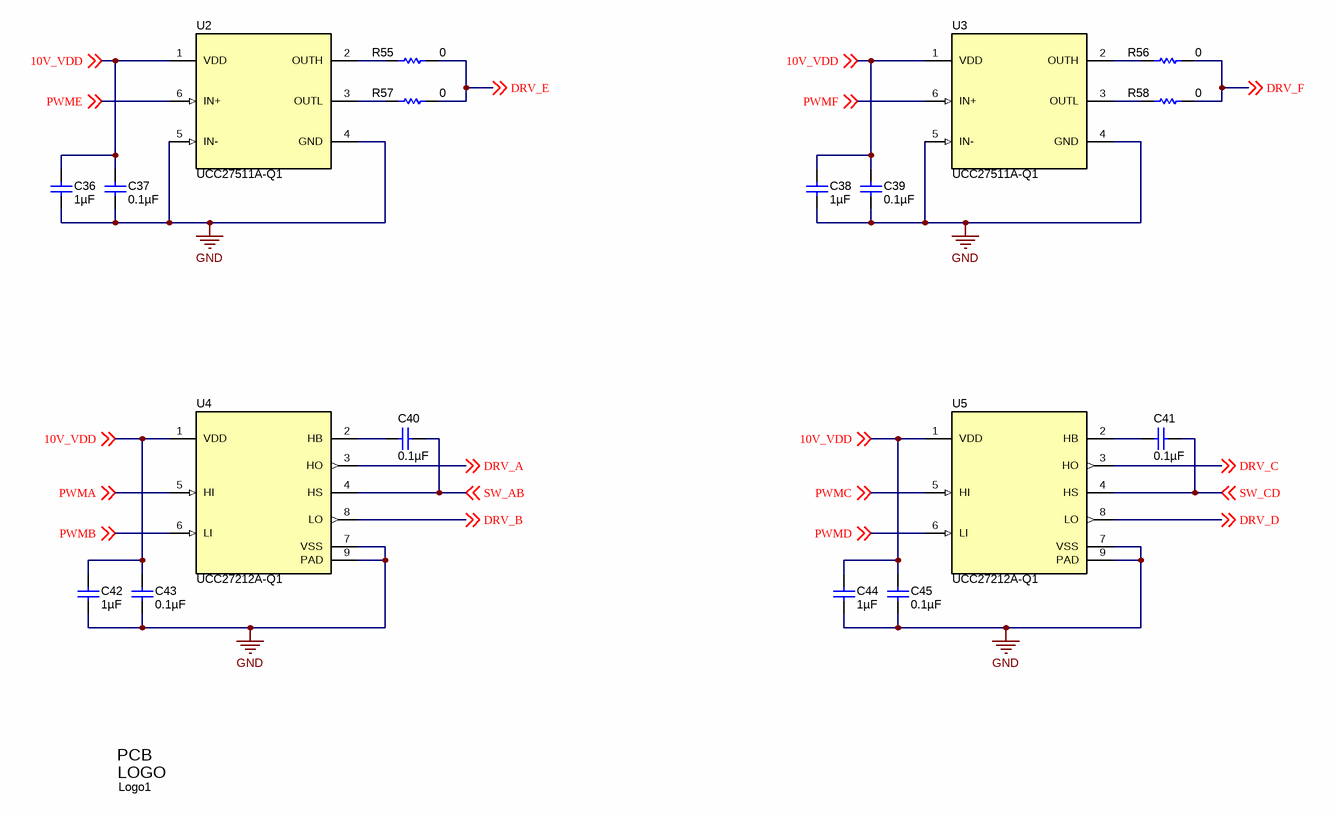
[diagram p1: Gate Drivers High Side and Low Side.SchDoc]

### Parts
C36  ValueDisplayed: 1µF  [0603L]  (hidden comment: GRM188R71E105KA12D)
C37  ValueDisplayed: 0.1µF  [0603L]  (hidden comment: GRM188R71H104KA93D)
C38  ValueDisplayed: 1µF  [0603L]  (hidden comment: GRM188R71E105KA12D)
C39  ValueDisplayed: 0.1µF  [0603L]  (hidden comment: GRM188R71H104KA93D)
C40  ValueDisplayed: 0.1µF  [0603L]  (hidden comment: GRM188R71H104KA93D)
C41  ValueDisplayed: 0.1µF  [0603L]  (hidden comment: GRM188R71H104KA93D)
C42  ValueDisplayed: 1µF  [0603L]  (hidden comment: GRM188R71E105KA12D)
C43  ValueDisplayed: 0.1µF  [0603L]  (hidden comment: GRM188R71H104KA93D)
C44  ValueDisplayed: 1µF  [0603L]  (hidden comment: GRM188R71E105KA12D)
C45  ValueDisplayed: 0.1µF  [0603L]  (hidden comment: GRM188R71H104KA93D)
Logo1  Pb-Free Symbol  [Pb-Free_Overlay_Medium]  (value not drawn)  (no BOM)
R55  ValueDisplayed: 0  [0603L]  (hidden comment: CRCW06030000Z0EA)
R56  ValueDisplayed: 0  [0603L]  (hidden comment: CRCW06030000Z0EA)
R57  ValueDisplayed: 0  [0603L]  (hidden comment: CRCW06030000Z0EA)
R58  ValueDisplayed: 0  [0603L]  (hidden comment: CRCW06030000Z0EA)
U2  UCC27511A-Q1  [DBV0006A_N]
U3  UCC27511A-Q1  [DBV0006A_N]
U4  UCC27212A-Q1  [DDA0008E_N]
U5  UCC27212A-Q1  [DDA0008E_N]

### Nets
GND: C36.2 C37.2 C38.2 C39.2 C42.2 C43.2 C44.2 C45.2 U2.4(GND) U2.5(IN-) U3.4(GND) U3.5(IN-) U4.7(VSS) U4.9(PAD) U5.7(VSS) U5.9(PAD)
10V_VDD: C36.1 C37.1 C38.1 C39.1 C42.1 C43.1 C44.1 C45.1 U2.1(VDD) U3.1(VDD) U4.1(VDD) U5.1(VDD) ; off-sheet 10V_VDD
DRV_A: U4.3(HO) ; off-sheet DRV_A
DRV_B: U4.8(LO) ; off-sheet DRV_B
DRV_C: U5.3(HO) ; off-sheet DRV_C
DRV_D: U5.8(LO) ; off-sheet DRV_D
DRV_E: R55.1 R57.1 ; off-sheet DRV_E
DRV_F: R56.1 R58.1 ; off-sheet DRV_F
PWMA: U4.5(HI) ; off-sheet PWMA
PWMB: U4.6(LI) ; off-sheet PWMB
PWMC: U5.5(HI) ; off-sheet PWMC
PWMD: U5.6(LI) ; off-sheet PWMD
PWME: U2.6(IN+) ; off-sheet PWME
PWMF: U3.6(IN+) ; off-sheet PWMF
SW_AB: C40.2 U4.4(HS) ; off-sheet SW_AB
SW_CD: C41.2 U5.4(HS) ; off-sheet SW_CD
NetC40_1: C40.1 U4.2(HB)
NetC41_1: C41.1 U5.2(HB)
NetR55_2: R55.2 U2.2(OUTH)
NetR56_2: R56.2 U3.2(OUTH)
NetR57_2: R57.2 U2.3(OUTL)
NetR58_2: R58.2 U3.3(OUTL)

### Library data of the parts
C36 C38 C42 C44 = GRM188R71E105KA12D: as C32 on sheet 400W Phase Shifted Full Bridge
C37 C39-C41 C43 C45 = GRM188R71H104KA93D: CAP, CERM, 0.1 µF, 50 V, +/- 10%, X7R, 0603; Manufacturer: MuRata; Polarized: N; CompType: Capacitor; Value: 0.1uF; U/M: EA; Cap_F: 0.0000001; Tolerance_%: 10; Value1: Unknown; VDC_V: 50; Value2: 50V; TaMin_C: -55; TaMax_C: 125; Cap_Case: 0603; SizeArea_mm2: 1.28; SizeAreaWB_mm2: 4.68; SizeX_mm: 1.6; SizeY_mm: 0.8; SizeZ_mm: 1; AEC Category: Q200
Logo1 = Pb-Free: SymbolCreator: a0412235
R55-R58 = CRCW06030000Z0EA: as R6 on sheet 400W Phase Shifted Full Bridge
U2 U3 = UCC27511DBVR: Single-Channel High-Speed Low-Side Gate Driver (with 4-A Peak Source and 8-A Peak Sink), DBV0006A (SOT-6); PartNumber: UCC27511AQDBVRQ1; Manufacturer: Texas Instruments; SymbolCreator: a0411947; SizeArea_mm2: 8.12; SizeAreaWB_mm2: 14.82; SizeX_mm: 2.8; SizeY_mm: 2.9; SizeZ_mm: 1.45; CompType: IC; U/M: EA
U4 U5 = UCC27211AQDDARQ1: 120-V Boot, 4-A Peak, High Frequency High-Side and Low-Side Driver, DDA0008E (SOIC-8); PartNumber: UCC27212AQDDARQ1; Manufacturer: Texas Instruments; SymbolCreator: a0411947; SizeArea_mm2: 31; SizeAreaWB_mm2: 57.4; SizeX_mm: 5; SizeY_mm: 6.2; SizeZ_mm: 1.7; CompType: IC; U/M: EA

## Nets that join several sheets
GND: 400W Phase Shifted Full Bridge (85 pins), Gate Drivers High Side and Low Side (16 pins)
10V_VDD: 400W Phase Shifted Full Bridge (C21.1 R31.2 TP4.1), Gate Drivers High Side and Low Side (12 pins)
DRV_A: 400W Phase Shifted Full Bridge (R6.1), Gate Drivers High Side and Low Side (U4.3)
DRV_B: 400W Phase Shifted Full Bridge (R19.1), Gate Drivers High Side and Low Side (U4.8)
DRV_C: 400W Phase Shifted Full Bridge (R8.1), Gate Drivers High Side and Low Side (U5.3)
DRV_D: 400W Phase Shifted Full Bridge (R21.1), Gate Drivers High Side and Low Side (U5.8)
DRV_E: 400W Phase Shifted Full Bridge (R1.2 R11.1 R13.1), Gate Drivers High Side and Low Side (R55.1 R57.1)
DRV_F: 400W Phase Shifted Full Bridge (R18.2 R24.1 R26.1), Gate Drivers High Side and Low Side (R56.1 R58.1)
PWMA: 400W Phase Shifted Full Bridge (U1.22), Gate Drivers High Side and Low Side (U4.5)
PWMB: 400W Phase Shifted Full Bridge (U1.21), Gate Drivers High Side and Low Side (U4.6)
PWMC: 400W Phase Shifted Full Bridge (U1.20), Gate Drivers High Side and Low Side (U5.5)
PWMD: 400W Phase Shifted Full Bridge (U1.19), Gate Drivers High Side and Low Side (U5.6)
PWME: 400W Phase Shifted Full Bridge (U1.18), Gate Drivers High Side and Low Side (U2.6)
PWMF: 400W Phase Shifted Full Bridge (U1.17), Gate Drivers High Side and Low Side (U3.6)
SW_AB: 400W Phase Shifted Full Bridge (12 pins), Gate Drivers High Side and Low Side (C40.2 U4.4)
SW_CD: 400W Phase Shifted Full Bridge (12 pins), Gate Drivers High Side and Low Side (C41.2 U5.4)

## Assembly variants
001: all parts fitted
